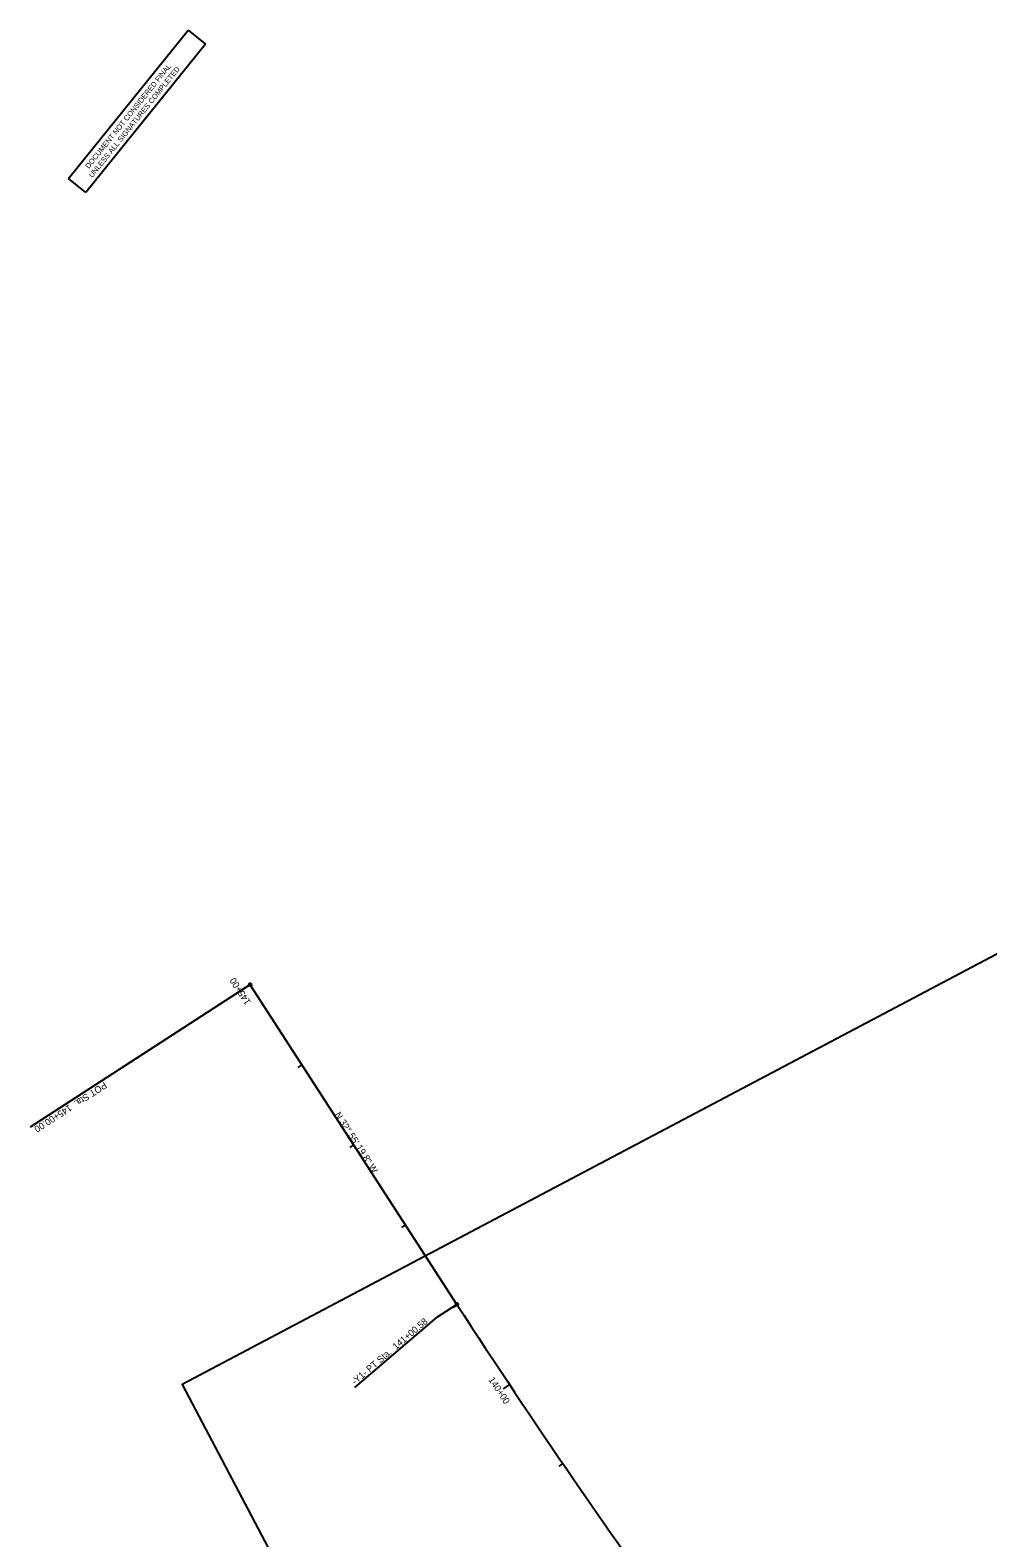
# Model space of a CAD drawing. Extents: x 1487008 to 1489561, y 497293 to 500195.
# Drawn here: x 1487008 to 1488013, y 498527 to 500108 of the extents above; entities that cross this region are included whole.
import ezdxf

# ---------------------------------------------------------------- set-up
doc = ezdxf.new("R2010")
doc.units = 0
for name, color, linetype in [('Prop Horizontal Alignment', 7, 'Continuous'), ('Prop Horizontal Alignment Direction Label', 7, 'Continuous'), ('Prop Horizontal Alignment Station Label', 7, 'Continuous'), ('Prop Horizontal Alignment Tick Label', 7, 'Continuous'), ('Prop Horizontal Alignment Tick Large', 7, 'Continuous'), ('Prop Horizontal Alignment Tick Small', 7, 'Continuous'), ('Scratch_Level_5', 7, 'Continuous'), ('Sheet Sticker Exception Certification CELL', 7, 'Continuous')]:
    doc.layers.add(name, color=color, linetype=linetype)

msp = doc.modelspace()

# ---------------------------------------------------------------- linework, layer by layer
at = {"layer": 'Prop Horizontal Alignment'}
msp.add_line((1487455.9, 498771.9), (1487238.8, 499107.2), dxfattribs=at)
msp.add_arc((1494171.2, 503119.9), 8000, 212.92217, 216.07943, dxfattribs=at)
at = {"layer": 'Prop Horizontal Alignment Station Label'}
for p, q in [((1487237.6, 499106.4), (1487008, 498957.7)), ((1487454.7, 498771.1), (1487435.1, 498758.4)), ((1487348.9, 498684.7), (1487435.1, 498758.4))]:
    msp.add_line(p, q, dxfattribs=at)
for centre in [(1487238.8, 499107.2), (1487455.9, 498771.9)]:
    msp.add_circle(centre, 1.5, dxfattribs=at)
at = {"layer": 'Prop Horizontal Alignment Tick Large'}
for p, q in [((1487238.8, 499107.2), (1487232.1, 499102.8)), ((1487511.1, 498687.8), (1487504.5, 498683.4))]:
    msp.add_line(p, q, dxfattribs=at)
at = {"layer": 'Prop Horizontal Alignment Tick Small'}
for p, q in [((1487293.2, 499023.2), (1487289, 499020.5)), ((1487347.5, 498939.3), (1487343.4, 498936.6)), ((1487401.9, 498855.4), (1487397.7, 498852.6)), ((1487456.2, 498771.4), (1487452.1, 498768.7)), ((1487567, 498604.9), (1487562.9, 498602.1))]:
    msp.add_line(p, q, dxfattribs=at)
at = {"layer": 'Scratch_Level_5'}
msp.add_lwpolyline([(1488170.1, 499217.2), (1487167.7, 498687.9), (1487657.1, 497758.9), (1488983.5, 498459.3), (1488907.6, 498603.2)], dxfattribs=at)
at = {"layer": 'Sheet Sticker Exception Certification CELL'}
for p, q in [((1487048.3, 499952.7), (1487173.9, 500108.5)), ((1487192.2, 500093.7), (1487066.6, 499938)), ((1487173.9, 500108.4), (1487192.2, 500093.7)), ((1487066.6, 499938), (1487048.3, 499952.7))]:
    msp.add_line(p, q, dxfattribs=at)

# ---------------------------------------------------------------- texts
at = {"layer": 'Prop Horizontal Alignment Direction Label'}
msp.add_text('N 32%%d 55\' 19.8" W', height=7, rotation=302.9222, dxfattribs=at).set_placement((1487327.3, 498970.9))
at = {"layer": 'Prop Horizontal Alignment Station Label'}
for s, rotation, p in [('POT Sta.  145+00.00', 212.9222, (1487085.6, 499005.6)), ('-Y1- PT Sta.  141+00.58', 40.5279, (1487349, 498687.1))]:
    msp.add_text(s, height=7, rotation=rotation, dxfattribs=at).set_placement(p)
at = {"layer": 'Prop Horizontal Alignment Tick Label'}
for s, rotation, p in [('145+00', 122.9222, (1487239.9, 499088.9)), ('140+00', 303.6425, (1487488.7, 498692.8))]:
    msp.add_text(s, height=7, rotation=rotation, dxfattribs=at).set_placement(p)
at = {"layer": 'Sheet Sticker Exception Certification CELL'}
for s, p in [('DOCUMENT NOT CONSIDERED FINAL', (1487069.6, 499962.7)), ('UNLESS ALL SIGNATURES COMPLETED', (1487073.3, 499953.2))]:
    msp.add_text(s, height=5.5, rotation=51.1156, dxfattribs=at).set_placement(p)

doc.saveas('drawing.dxf')
